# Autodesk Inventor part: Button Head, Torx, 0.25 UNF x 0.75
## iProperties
Author: Administrator
Shininess: 25.0
PropertySet Name: _Private Model Information
Created: 2001-03
Part Number: Button Head, Torx, 0.25 UNF x 0.75
Material: Steel, Mild
Description: Button Head, Torx, 0.25 UNF x 0.75
Document SubType Name: Modeling
Designer: Administrator
Control State: 0
Master: False
Checked Out: False
PropertySet Name: Design Tracking Control
Density: 7.86
Volumn: 1.0470389527034538
Area: 8.192112949038872
PropertySet Name: Model Information
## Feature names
1. Revolution1
2. Hex [Extrusion]
3. Chamfer1
4. Torx [Extrusion]
